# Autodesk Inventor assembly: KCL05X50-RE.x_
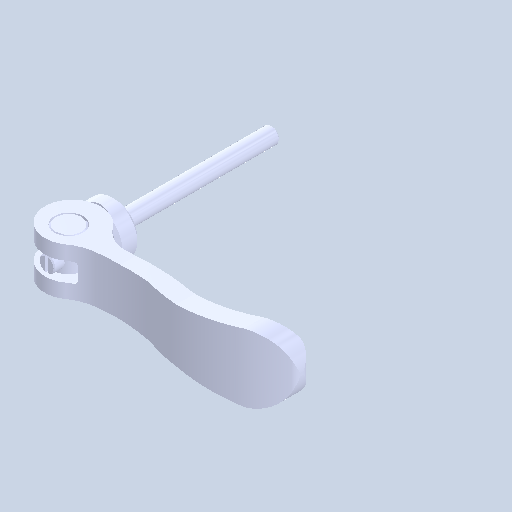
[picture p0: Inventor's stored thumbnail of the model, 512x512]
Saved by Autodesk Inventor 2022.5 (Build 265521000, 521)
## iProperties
Created: 2024-08
Part Number: KCL05X50-RE.x_
Document SubType Name: Assembly
Designer: ImaoCorp
Author: ImaoCorp
Sending System: SOLIDWORKS 2022-2022290
MC: AMD64
MC_MODEL: Intel64 Family 6 Model 60 Stepping 3, GenuineIntel
OS: Windows_NT
FRU: Parasolid Version 33.1, build 260,  4-25-2022
FORMAT: text
GUISE: transmit
KEY: FILEKCL05X50-RE.x_t
DATE: Thu Aug 29 10:49:22 2024
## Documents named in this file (5)
- Y:\5.更新分\2024年対応\1001_KCL\データ\kcl05x50-re\KCL05X50-RE.x_.iam
- Y:\5.更新分\2024年対応\1001_KCL\データ\kcl05x50-re\KCL05X50-RE_01.ipt
- Y:\5.更新分\2024年対応\1001_KCL\データ\kcl05x50-re\KCL05X50-RE_02.ipt
- Y:\5.更新分\2024年対応\1001_KCL\データ\kcl05x50-re\KCL05X50-RE_03.ipt
- Y:\5.更新分\2024年対応\1001_KCL\データ\kcl05x50-re\KCL05X50-RE_04.ipt
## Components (4 placed, 4 different names)
1. KCL05X50-RE_01
2. KCL05X50-RE_02
3. KCL05X50-RE_03
4. KCL05X50-RE_04
